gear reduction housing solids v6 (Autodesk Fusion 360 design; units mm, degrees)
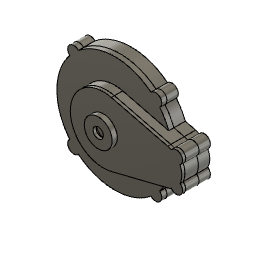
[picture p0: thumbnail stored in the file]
parameter "Drive_Gear_Dia" = 96 (= "( ( Drive_Gear_Teeth * Gear_Module ) * 1 mm )")
parameter "Driven_Gear_Dia" = 32 (= "( ( Driven_Gear_Teeth * Gear_Module ) * 1 mm )")
parameter "Idle_Gear_Dia" = 20 (= "( ( Idle_Gear_Teeth * Gear_Module ) * 1 mm )")
parameter "Mount_Bolts" = 8
parameter "Idle_Gear_Shaft" = 8
parameter "Mount_Bolt_Flange" = 12
parameter "Gear_Clearance_Dia" = 8
parameter "Gear_Thickness" = 8
parameter "Idle_Gear_Thickness" = 21
parameter "Housing_Wall_Thickness" = 3
parameter "Gear_Gap" = 5
sketch "Layout Sketch" plane through (0, 0, 0) normal (0, 0, 1) x axis (1, 0, 0)
  circle C1 centre (0, 0) radius 48
  circle C2 centre (0, 0) radius 16
  circle C3 centre (22.6316, 12.7989) radius 10
  circle C4 centre (38, 0) radius 10
  circle C5 centre (58, 0) radius 10
  point P1 (0, 0)
  point P2 (0, 0)
  point P3 (0, 0)
  point P6 (58, 0)
  point P5 (38, 0)
  coincident P1 P2
  concentric C1 C2
  horizontal P3 P6
  tangent C2 C3
  tangent C3 C4
  tangent C1 C5
  tangent C1 C4
  horizontal P3 P5
  dimension "d15" diameter C1 = 96 (= "Drive_Gear_Dia")
  dimension "d16" diameter C2 = 32 (= "Driven_Gear_Dia")
  dimension "d17" diameter C3 = 20 (= "Idle_Gear_Dia")
  dimension "d18" diameter C5 = 20 (= "Idle_Gear_Dia")
  dimension "d19" diameter C4 = 20 (= "Idle_Gear_Dia")
sketch "Housing Layout Sketch" plane through (0, 0, 0) normal (0, 0, 1) x axis (1, 0, 0)
  line L1 (62.3448, 17.4678) -> (7.7241, 31.0538)
  line L2 (7.7241, -31.0538) -> (62.3448, -17.4678)
  line L3 (39.598, -39.598) -> (0, 0)
  line L4 (70.7279, -12.7279) -> (58, 0)
  line L5 (0, 40.8023) -> (0, 0)
  line L6 (-24.8762, 0) -> (0, 0)
  circle C1 centre (0, 0) radius 48
  circle C2 centre (0, 0) radius 16
  circle C3 centre (22.6316, 12.7989) radius 10
  circle C4 centre (38, 0) radius 10
  circle C5 centre (58, 0) radius 10
  circle C6 centre (0, 0) radius 52
  circle C7 centre (0, 0) radius 56
  circle C8 centre (0, 0) radius 32
  circle C9 centre (58, 0) radius 18
  circle C10 centre (0, 0) radius 5
  circle C11 centre (22.6316, 12.7989) radius 4
  circle C12 centre (38, 0) radius 4
  circle C13 centre (58, 0) radius 4
  circle C14 centre (39.598, -39.598) radius 6
  circle C15 centre (39.598, -39.598) radius 4
  circle C16 centre (70.7279, -12.7279) radius 6
  circle C17 centre (70.7279, -12.7279) radius 4
  circle C18 centre (-39.598, -39.598) radius 6
  circle C19 centre (-39.598, -39.598) radius 4
  circle C20 centre (-39.598, 39.598) radius 4
  circle C21 centre (-39.598, 39.598) radius 6
  circle C22 centre (39.598, 39.598) radius 4
  circle C23 centre (39.598, 39.598) radius 6
  circle C24 centre (70.7279, 12.7279) radius 4
  circle C25 centre (70.7279, 12.7279) radius 6
  point P11 (7.7241, 31.0538)
  point P12 (62.3448, 17.4678)
  point P13 (62.3448, -17.4678)
  point P14 (7.7241, -31.0538)
  point P19 (39.598, -39.598)
  point P21 (70.7279, -12.7279)
  point P15 (0, 0)
  point P23 (0, 0)
  point P20 (39.598, -39.598)
  point P24 (39.598, -39.598)
  point P18 (58, 0)
  point P25 (58, 0)
  point P26 (70.7279, -12.7279)
  point P8 (0, 0)
  point P27 (0, 0)
  point P29 (-39.598, -39.598)
  point P3 (0, 0)
  point P31 (0, 0)
  concentric C2 C6
  concentric C6 C7
  concentric C6 C8
  concentric C5 C9
  coincident C8 P11
  coincident C9 P12
  coincident C9 P13
  coincident C8 P14
  tangent C8 L1
  tangent C9 L1
  tangent C9 L2
  tangent C8 L2
  concentric C1 C10
  concentric C3 C11
  concentric C4 C12
  concentric C5 C13
  coincident C7 P19
  concentric C14 C15
  coincident C9 P21
  concentric C16 C17
  coincident P15 P23
  coincident P20 P24
  coincident P18 P25
  coincident P21 P26
  coincident P8 P27
  vertical L5
  coincident C7 P29
  concentric C18 C19
  symmetric C14 L5 C18
  symmetric C15 L5 C19
  coincident P3 P31
  horizontal L6
  symmetric C14 L6 C23
  symmetric C15 L6 C22
  symmetric C16 L6 C25
  symmetric C17 L6 C24
  symmetric C18 L6 C21
  symmetric C19 L6 C20
  dimension "d21" distance C1 C7 = 8 (= "Gear_Clearance_Dia")
  dimension "d22" distance C5 C9 = 8 (= "Gear_Clearance_Dia")
  dimension "d23" distance C2 C8 = 16 (= "Gear_Clearance_Dia * 2")
  dimension "d24" diameter C10 = 10
  dimension "d25" diameter C11 = 8 (= "Idle_Gear_Shaft")
  dimension "d26" diameter C12 = 8 (= "Idle_Gear_Shaft")
  dimension "d27" diameter C13 = 8 (= "Idle_Gear_Shaft")
  dimension "d28" angle L3 L5 = 45
  dimension "d29" angle L4 L5 = 45 (= "d28")
  dimension "d30" diameter C15 = 8 (= "Mount_Bolts")
  dimension "d31" diameter C17 = 8 (= "Mount_Bolts")
  dimension "d32" distance C14 C15 = 2
  dimension "d33" distance C16 C17 = 2 (= "d32")
work_plane "WorkPlane1"
work_plane "WorkPlane2" AlongDistance 5 (= "Gear_Gap")
work_plane "WorkPlane3" AlongDistance 13 (= "Gear_Gap + Gear_Thickness")
extrude "Extrude1" new body sketch "Housing Layout Sketch" profile of C6 C7 C8 C9 L1 L2 C10 C11 C12 C13 C14 C15 C16 C17 C18 C19 C20 C21 C22 C23 C24 C25 to an object bodies "Back Housing"
extrude "Extrude2" new body of existing geometry to an object bodies "Front Housing"
extrude "Extrude3" add sketch "Housing Layout Sketch" profile of C6 C7 C8 C9 L1 L2 C10 C11 C12 C13 C16 C17 C24 C25 to an object
sketch "Sketch4" plane through (0, 0, 13) normal (0, 0, 1) x axis (1, 0, 0)
  line L1 (62.3448, -17.4678) -> (7.7241, -31.0538)
  line L2 (7.7241, 31.0538) -> (62.3448, 17.4678)
  line L3 (62.3448, 17.4678) -> (7.7241, 31.0538)
  line L4 (7.7241, -31.0538) -> (62.3448, -17.4678)
  line L5 (7, 28.1425) -> (61.6207, 14.5565)
  line L6 (61.6207, -14.5565) -> (7, -28.1425)
  arc A1 centre (58, 0) radius 18 clockwise from (65.8375, -16.2041) to (62.3448, -17.4678)
  arc A2 centre (70.7279, -12.7279) radius 6 clockwise from (74.2041, -7.8375) to (65.8375, -16.2041)
  arc A3 centre (58, 0) radius 18 clockwise from (74.2041, 7.8375) to (74.2041, -7.8375)
  arc A4 centre (70.7279, 12.7279) radius 6 clockwise from (65.8375, 16.2041) to (74.2041, 7.8375)
  arc A5 centre (58, 0) radius 18 clockwise from (62.3448, 17.4678) to (65.8375, 16.2041)
  arc A6 centre (0, 0) radius 32 clockwise from (7.7241, -31.0538) to (7.7241, 31.0538)
  circle C1 centre (58, 0) radius 18
  circle C2 centre (0, 0) radius 32
  arc A7 centre (0, 0) radius 32 clockwise from (7.7241, -31.0538) to (7.7241, 31.0538)
  arc A8 centre (58, 0) radius 18 clockwise from (62.3448, 17.4678) to (62.3448, -17.4678)
  arc A9 centre (58, 0) radius 15 clockwise from (61.6207, 14.5565) to (61.6207, -14.5565)
  arc A10 centre (0, 0) radius 29 clockwise from (7, -28.1425) to (7, 28.1425)
  point P15 (7.7241, 31.0538)
  point P16 (62.3448, 17.4678)
  concentric C2 A7
  coincident P15 A7
  concentric C1 A8
  coincident P16 A8
extrude "Extrude5" new body of existing geometry blind 3 (= "Housing_Wall_Thickness")
extrude "Extrude4" cut sketch "Sketch4" profile of A9 L6 L5 A10 to an object
sketch "Sketch5" plane through (0, 0, 0) normal (0, 0, 1) x axis (1, 0, 0)
  line L1 (52.3217, 19.9608) -> (62.3448, 17.4678)
  line L2 (62.3448, -17.4678) -> (52.3217, -19.9608)
  line L3 (62.3448, 17.4678) -> (52.3217, 19.9608)
  line L4 (52.3217, -19.9608) -> (62.3448, -17.4678)
  line L5 (51.5976, 17.0495) -> (61.6207, 14.5565)
  line L6 (61.6207, -14.5565) -> (51.5976, -17.0495)
  line L7 (48.8862, 17.724) -> (51.5976, 17.0495)
  line L8 (48.8862, -17.724) -> (51.5976, -17.0495)
  arc A1 centre (58, 0) radius 18 clockwise from (65.8375, -16.2041) to (62.3448, -17.4678)
  arc A2 centre (70.7279, -12.7279) radius 6 clockwise from (74.2041, -7.8375) to (65.8375, -16.2041)
  arc A3 centre (58, 0) radius 18 clockwise from (74.2041, 7.8375) to (74.2041, -7.8375)
  arc A4 centre (70.7279, 12.7279) radius 6 clockwise from (65.8375, 16.2041) to (74.2041, 7.8375)
  arc A5 centre (58, 0) radius 18 clockwise from (62.3448, 17.4678) to (65.8375, 16.2041)
  arc A6 centre (0, 0) radius 56 clockwise from (43.6072, 35.1341) to (52.3217, 19.9608)
  arc A7 centre (39.598, 39.598) radius 6 clockwise from (35.1341, 43.6072) to (43.6072, 35.1341)
  arc A8 centre (0, 0) radius 56 clockwise from (-35.1341, 43.6072) to (35.1341, 43.6072)
  arc A9 centre (-39.598, 39.598) radius 6 clockwise from (-43.6072, 35.1341) to (-35.1341, 43.6072)
  arc A10 centre (0, 0) radius 56 clockwise from (-43.6072, -35.1341) to (-43.6072, 35.1341)
  arc A11 centre (-39.598, -39.598) radius 6 clockwise from (-35.1341, -43.6072) to (-43.6072, -35.1341)
  arc A12 centre (0, 0) radius 56 clockwise from (35.1341, -43.6072) to (-35.1341, -43.6072)
  arc A13 centre (39.598, -39.598) radius 6 clockwise from (43.6072, -35.1341) to (35.1341, -43.6072)
  arc A14 centre (0, 0) radius 56 clockwise from (52.3217, -19.9608) to (43.6072, -35.1341)
  circle C1 centre (-39.598, 39.598) radius 6
  circle C2 centre (-39.598, -39.598) radius 6
  circle C3 centre (39.598, -39.598) radius 6
  circle C4 centre (0, 0) radius 52
  circle C5 centre (39.598, 39.598) radius 6
  circle C6 centre (70.7279, 12.7279) radius 6
  circle C7 centre (70.7279, -12.7279) radius 6
  circle C8 centre (58, 0) radius 18
  circle C9 centre (58, 0) radius 15
  point P43 (48.8862, 17.724)
  point P44 (48.8862, -17.724)
  coincident C4 P43
  parallel L5 L7
  coincident C4 P44
  parallel L6 L8
extrude "Extrude6" cut sketch "Sketch5" profile of C1 C2 C3 C4 C5 C6 C7 C8 C9 L5 L6 L7 L8 no distance stored
sketch "Sketch6" plane through (0, 0, 5) normal (0, 0, 1) x axis (1, 0, 0)
  line L1 (7, 28.1425) -> (61.6207, 14.5565)
  line L2 (61.6207, -14.5565) -> (7, -28.1425)
  arc A1 centre (58, 0) radius 15 clockwise from (61.6207, 14.5565) to (61.6207, -14.5565)
  arc A2 centre (0, 0) radius 29 clockwise from (7, -28.1425) to (7, 28.1425)
  circle C1 centre (0, 0) radius 10.5
  point P1 (0, 0)
  point P8 (0, 0)
  coincident P1 P8
  dimension "d57" diameter C1 = 21
extrude "Extrude7" cut sketch "Sketch6" profile of C1 no distance stored
sketch "Sketch7" plane through (0, 0, 16) normal (0, 0, 1) x axis (1, 0, 0)
  line L1 (62.3448, -17.4678) -> (7.7241, -31.0538)
  line L2 (7.7241, 31.0538) -> (62.3448, 17.4678)
  circle C1 centre (0, 0) radius 10.5
  arc A1 centre (58, 0) radius 18 clockwise from (65.8375, -16.2041) to (62.3448, -17.4678)
  arc A2 centre (70.7279, -12.7279) radius 6 clockwise from (74.2041, -7.8375) to (65.8375, -16.2041)
  arc A3 centre (58, 0) radius 18 clockwise from (74.2041, 7.8375) to (74.2041, -7.8375)
  arc A4 centre (70.7279, 12.7279) radius 6 clockwise from (65.8375, 16.2041) to (74.2041, 7.8375)
  arc A5 centre (58, 0) radius 18 clockwise from (62.3448, 17.4678) to (65.8375, 16.2041)
  arc A6 centre (0, 0) radius 32 clockwise from (7.7241, -31.0538) to (7.7241, 31.0538)
  circle C2 centre (0, 0) radius 13.5
  circle C3 centre (0, 0) radius 5
  point P1 (0, 0)
  point P14 (0, 0)
  coincident P1 P14
  concentric C2 C3
  dimension "d60" distance C1 C2 = 3 (= "Housing_Wall_Thickness")
  dimension "d61" diameter C3 = 10
extrude "Extrude8" new body sketch "Sketch7" profile of C1 C2 along normal blind 2
extrude "Extrude9" sketch "Sketch7" profile of C1 C2 C3 blind 3 (= "Housing_Wall_Thickness") bodies "Front Cover"
combine "Combine1"
sketch "Sketch8" plane through (0, 0, 0) normal (1, 0, 0) x axis (0, 1, 0)
  line L1 (0, -21.1188) -> (0, 0)
  line L2 (-10.5, -11) -> (-56, -11)
  line L3 (56, -11) -> (10.5, -11)
  line L4 (-10.5, -8) -> (-10.5, -11)
  line L5 (10.5, -11) -> (10.5, -8)
  line L6 (10.5, -13) -> (10.5, -11)
  line L7 (5, -13) -> (10.5, -13)
  line L8 (5, -16) -> (5, -13)
  line L9 (13.5, -16) -> (5, -16)
  line L10 (13.5, -11) -> (13.5, -16)
  point P1 (0, 0)
  point P2 (0, 0)
  point P6 (10.5, -11)
  point P12 (10.5, -11)
  point P17 (13.5, -11)
  point P14 (5, -13)
  point P15 (5, -16)
  point P10 (10.5, -8)
  point P13 (10.5, -13)
  coincident P1 P2
  vertical L1
  coincident P6 P12
  perpendicular L3 L6
  perpendicular L6 L7
  perpendicular L7 L8
  perpendicular L8 L9
  coincident L3 P17
  perpendicular L3 L10
  dimension "d67" distance L6 L10 = 3 (= "Housing_Wall_Thickness")
  dimension "d68" distance P14 P15 = 3 (= "Housing_Wall_Thickness")
  dimension "d69" = 10
  dimension "d70" distance P10 P13 = 5
revolve "Revolve1" sketch "Sketch8" AlongAngle 360
named bodies: "Back Housing", "Front Housing", "Front Cover"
